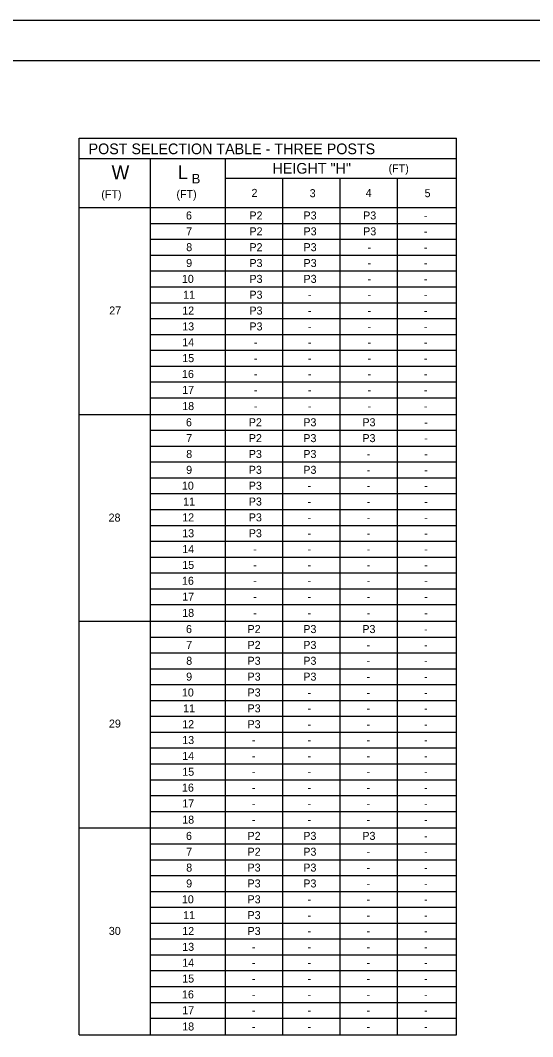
# Model space of a CAD drawing. Extents: x -2340 to 628, y -879 to 309.
# Drawn here: x -61.9 to 130.1, y -71.4 to 309.4 of the extents above; entities that cross this region are included whole.
import ezdxf

# ---------------------------------------------------------------- set-up
doc = ezdxf.new("R2010")
doc.units = 0
for name, color, linetype in [('Level 1', 7, 'Continuous'), ('Level 2', 7, 'Continuous'), ('PLT-BNDY', 7, 'Continuous')]:
    doc.layers.add(name, color=color, linetype=linetype)

msp = doc.modelspace()

# ---------------------------------------------------------------- linework, layer by layer
at = {"layer": 'Level 1'}
for p, q in [((-236.39, 294.44), (549.61, 294.44)), ((-39.86, 239.28), (-39.86, 265.3)), ((-39.86, 265.3), (101.61, 265.3)), ((101.61, 239.28), (101.61, 265.3)), ((-39.86, 257.63), (101.61, 257.63)), ((-13.06, -70.68), (-13.06, 257.63)), ((14.94, 239.28), (14.94, 257.63)), ((36.44, -70.68), (36.44, 250.28)), ((57.94, -70.68), (57.94, 250.28)), ((79.44, -70.68), (79.44, 250.28)), ((-39.86, -70.68), (-39.86, 239.28)), ((-39.86, 239.28), (101.61, 239.28)), ((14.94, -70.68), (14.94, 239.28)), ((101.61, -70.68), (101.61, 239.28))]:
    msp.add_line(p, q, dxfattribs=at)
at = {"layer": 'Level 2'}
for p, q in [((14.94, 250.28), (101.61, 250.28)), ((-13.06, 233.34), (101.61, 233.34)), ((-13.06, 227.4), (101.61, 227.4)), ((-13.06, 221.46), (101.61, 221.46)), ((53.29, 221.46), (97.57, 221.46)), ((-13.06, 215.52), (101.61, 215.52)), ((53.29, 215.52), (97.57, 215.52)), ((-13.06, 209.58), (101.61, 209.58)), ((53.29, 209.58), (97.57, 209.58)), ((-13.06, 203.64), (101.61, 203.64)), ((53.29, 203.64), (97.57, 203.64)), ((-13.06, 197.7), (101.61, 197.7)), ((53.29, 197.7), (97.57, 197.7)), ((-13.06, 191.76), (101.61, 191.76)), ((53.29, 191.76), (97.57, 191.76)), ((-13.06, 185.82), (101.61, 185.82)), ((53.29, 185.82), (97.57, 185.82)), ((-13.06, 179.88), (101.61, 179.88)), ((53.29, 179.88), (97.57, 179.88)), ((-13.06, 173.94), (101.61, 173.94)), ((53.29, 173.94), (97.57, 173.94)), ((-13.06, 168), (101.61, 168)), ((-39.86, 161.79), (101.61, 161.79)), ((-13.06, 155.85), (101.61, 155.85)), ((-13.06, 149.91), (101.61, 149.91)), ((53.29, 149.91), (97.57, 149.91)), ((-13.06, 143.97), (101.61, 143.97)), ((-13.06, 138.03), (101.61, 138.03)), ((53.29, 138.03), (97.57, 138.03)), ((-13.06, 132.09), (101.61, 132.09)), ((53.29, 132.09), (97.57, 132.09)), ((-13.06, 126.15), (101.61, 126.15)), ((-13.06, 120.21), (101.61, 120.21)), ((-13.06, 114.27), (101.61, 114.27)), ((-13.06, 108.33), (101.61, 108.33)), ((-13.06, 102.39), (101.61, 102.39)), ((-13.06, 96.45), (101.61, 96.45)), ((-13.06, 90.51), (101.61, 90.51)), ((-39.86, 84.3), (101.61, 84.3)), ((-13.06, 78.36), (101.61, 78.36)), ((-13.06, 72.42), (101.61, 72.42)), ((-13.06, 66.48), (101.61, 66.48)), ((97.57, 66.48), (101.61, 66.48)), ((-13.06, 60.54), (101.61, 60.54)), ((-13.06, 54.6), (101.61, 54.6)), ((-13.06, 48.66), (101.61, 48.66)), ((-13.06, 42.72), (101.61, 42.72)), ((-13.06, 36.78), (101.61, 36.78)), ((-13.06, 30.84), (101.61, 30.84)), ((-13.06, 24.9), (101.61, 24.9)), ((-13.06, 18.96), (101.61, 18.96)), ((-13.06, 13.02), (101.61, 13.02)), ((-39.86, 6.81), (101.61, 6.81)), ((-13.06, 0.87), (101.61, 0.87)), ((-13.06, -5.07), (101.61, -5.07)), ((-13.06, -11.01), (101.61, -11.01)), ((-13.06, -16.95), (101.61, -16.95)), ((-13.06, -22.89), (101.61, -22.89)), ((-13.06, -28.83), (101.61, -28.83)), ((-13.06, -34.77), (101.61, -34.77)), ((-13.06, -40.71), (101.61, -40.71)), ((-13.06, -46.65), (101.61, -46.65)), ((-13.06, -52.59), (101.61, -52.59)), ((-13.06, -58.53), (101.61, -58.53)), ((-13.06, -64.47), (101.61, -64.47)), ((-39.86, -70.68), (101.61, -70.68))]:
    msp.add_line(p, q, dxfattribs=at)
at = {"layer": 'PLT-BNDY'}
msp.add_lwpolyline([(-276.39, 309.44), (564.61, 309.44), (564.61, -284.56), (-276.39, -284.56)], close=True, dxfattribs=at)

# ---------------------------------------------------------------- texts
at = {"layer": 'Level 1'}
for s, height, p in [('POST SELECTION TABLE - THREE POSTS', 4.003, (-36.3, 259.28)), ('HEIGHT "H"', 4.003, (32.63, 251.98)), ('(FT)', 3, (76.11, 252.49)), ('W', 5.25, (-27.68, 249.85)), ('L', 5.16, (-2.92, 249.96)), ('B', 3.6, (2.36, 248.3)), ('(FT)', 3, (-31.53, 242.76)), ('(FT)', 3, (-3.39, 242.82))]:
    msp.add_text(s, height=height, dxfattribs=at).set_placement(p)
for s, p in [('2', (24.75, 243.27)), ('3', (46.54, 243.17)), ('4', (67.52, 243.27)), ('5', (89.59, 243.17))]:
    msp.add_text(s, height=3, rotation=360, dxfattribs=at).set_placement(p)
at = {"layer": 'Level 2'}
for s, p in [('6', (0.19, 234.82)), ('P2', (23.96, 234.82)), ('P3', (44.23, 234.82)), ('P3', (66.57, 234.82)), ('-', (89.28, 234.82)), ('7', (0.28, 228.88)), ('P2', (23.96, 228.88)), ('P3', (44.23, 228.88)), ('P3', (66.57, 228.88)), ('-', (89.28, 228.88)), ('8', (0.28, 222.94)), ('P2', (23.96, 222.94)), ('P3', (44.23, 222.94)), ('-', (68.19, 222.94)), ('-', (89.28, 222.94)), ('9', (0.26, 217)), ('P3', (23.96, 217)), ('P3', (44.23, 217)), ('-', (68.19, 217)), ('-', (89.28, 217)), ('10', (-1.35, 211.06)), ('P3', (23.96, 211.06)), ('P3', (44.23, 211.06)), ('-', (68.19, 211.06)), ('-', (89.28, 211.06)), ('11', (-0.88, 205.12)), ('P3', (23.96, 205.12)), ('-', (45.84, 205.12)), ('-', (68.19, 205.12)), ('-', (89.28, 205.12)), ('27', (-28.56, 199.21)), ('12', (-1.22, 199.18)), ('P3', (23.96, 199.18)), ('-', (45.84, 199.18)), ('-', (68.19, 199.18)), ('-', (89.28, 199.18)), ('13', (-1.22, 193.24)), ('P3', (23.96, 193.24)), ('-', (45.84, 193.24)), ('-', (68.19, 193.24)), ('-', (89.28, 193.24)), ('14', (-1.22, 187.3)), ('-', (25.58, 187.3)), ('-', (45.84, 187.3)), ('-', (68.19, 187.3)), ('-', (89.28, 187.3)), ('15', (-1.22, 181.36)), ('-', (25.58, 181.36)), ('-', (45.84, 181.36)), ('-', (68.19, 181.36)), ('-', (89.28, 181.36)), ('16', (-1.31, 175.42)), ('-', (25.58, 175.42)), ('-', (45.84, 175.42)), ('-', (68.19, 175.42)), ('-', (89.28, 175.42)), ('17', (-1.22, 169.48)), ('-', (25.58, 169.48)), ('-', (45.84, 169.48)), ('-', (68.19, 169.48)), ('-', (89.28, 169.48)), ('18', (-1.22, 163.4)), ('-', (25.58, 163.4)), ('-', (45.84, 163.4)), ('-', (68.19, 163.4)), ('-', (89.28, 163.4)), ('6', (0.19, 157.33)), ('P2', (23.72, 157.33)), ('P3', (44.15, 157.33)), ('P3', (66.29, 157.33)), ('-', (89.49, 157.33)), ('7', (0.28, 151.39)), ('P2', (23.72, 151.39)), ('P3', (44.15, 151.39)), ('P3', (66.29, 151.39)), ('-', (89.49, 151.39)), ('8', (0.28, 145.45)), ('P3', (23.72, 145.45)), ('P3', (44.15, 145.45)), ('-', (67.91, 145.45)), ('-', (89.49, 145.45)), ('9', (0.26, 139.51)), ('P3', (23.72, 139.51)), ('P3', (44.15, 139.51)), ('-', (67.91, 139.51)), ('-', (89.49, 139.51)), ('10', (-1.35, 133.57)), ('P3', (23.72, 133.57)), ('-', (45.77, 133.57)), ('-', (67.91, 133.57)), ('-', (89.49, 133.57)), ('11', (-0.88, 127.63)), ('P3', (23.72, 127.63)), ('-', (45.77, 127.63)), ('-', (67.91, 127.63)), ('-', (89.49, 127.63)), ('28', (-28.81, 121.62)), ('12', (-1.22, 121.69)), ('P3', (23.72, 121.69)), ('-', (45.77, 121.69)), ('-', (67.91, 121.69)), ('-', (89.49, 121.69)), ('13', (-1.22, 115.75)), ('P3', (23.72, 115.75)), ('-', (45.77, 115.75)), ('-', (67.91, 115.75)), ('-', (89.49, 115.75)), ('14', (-1.22, 109.81)), ('-', (25.34, 109.81)), ('-', (45.77, 109.81)), ('-', (67.91, 109.81)), ('-', (89.49, 109.81)), ('15', (-1.22, 103.87)), ('-', (25.34, 103.87)), ('-', (45.77, 103.87)), ('-', (67.91, 103.87)), ('-', (89.49, 103.87)), ('16', (-1.31, 97.93)), ('-', (25.34, 97.93)), ('-', (45.77, 97.93)), ('-', (67.91, 97.93)), ('-', (89.49, 97.93)), ('17', (-1.22, 91.99)), ('-', (25.34, 91.99)), ('-', (45.77, 91.99)), ('-', (67.91, 91.99)), ('-', (89.49, 91.99)), ('18', (-1.22, 85.91)), ('-', (25.34, 85.91)), ('-', (45.77, 85.91)), ('-', (67.91, 85.91)), ('-', (89.49, 85.91)), ('6', (0.19, 79.84)), ('P2', (23.25, 79.84)), ('P3', (44.15, 79.84)), ('P3', (66.27, 79.84)), ('-', (89.39, 79.84)), ('7', (0.28, 73.9)), ('P2', (23.25, 73.9)), ('P3', (44.15, 73.9)), ('-', (67.89, 73.9)), ('-', (89.39, 73.9)), ('8', (0.28, 67.96)), ('P3', (23.25, 67.96)), ('P3', (44.15, 67.96)), ('-', (67.89, 67.96)), ('-', (89.39, 67.96)), ('9', (0.26, 62.02)), ('P3', (23.25, 62.02)), ('P3', (44.15, 62.02)), ('-', (67.89, 62.02)), ('-', (89.39, 62.02)), ('10', (-1.35, 56.08)), ('P3', (23.25, 56.08)), ('-', (45.77, 56.08)), ('-', (67.89, 56.08)), ('-', (89.39, 56.08)), ('11', (-0.88, 50.14)), ('P3', (23.25, 50.14)), ('-', (45.77, 50.14)), ('-', (67.89, 50.14)), ('-', (89.39, 50.14)), ('29', (-28.68, 44.43)), ('12', (-1.22, 44.2)), ('P3', (23.25, 44.2)), ('-', (45.77, 44.2)), ('-', (67.89, 44.2)), ('-', (89.39, 44.2)), ('13', (-1.22, 38.26)), ('-', (24.87, 38.26)), ('-', (45.77, 38.26)), ('-', (67.89, 38.26)), ('-', (89.39, 38.26)), ('14', (-1.22, 32.32)), ('-', (24.87, 32.32)), ('-', (45.77, 32.32)), ('-', (67.89, 32.32)), ('-', (89.39, 32.32)), ('15', (-1.22, 26.38)), ('-', (24.87, 26.38)), ('-', (45.77, 26.38)), ('-', (67.89, 26.38)), ('-', (89.39, 26.38)), ('16', (-1.31, 20.44)), ('-', (24.87, 20.44)), ('-', (45.77, 20.44)), ('-', (67.89, 20.44)), ('-', (89.39, 20.44)), ('17', (-1.22, 14.5)), ('-', (24.87, 14.5)), ('-', (45.77, 14.5)), ('-', (67.89, 14.5)), ('-', (89.39, 14.5)), ('18', (-1.22, 8.42)), ('-', (24.87, 8.42)), ('-', (45.77, 8.42)), ('-', (67.89, 8.42)), ('-', (89.39, 8.42)), ('6', (0.19, 2.35)), ('P2', (23.25, 2.35)), ('P3', (44.15, 2.35)), ('P3', (66.27, 2.35)), ('-', (89.39, 2.35)), ('7', (0.28, -3.59)), ('P2', (23.25, -3.59)), ('P3', (44.15, -3.59)), ('-', (67.89, -3.59)), ('-', (89.39, -3.59)), ('8', (0.28, -9.53)), ('P3', (23.25, -9.53)), ('P3', (44.15, -9.53)), ('-', (67.89, -9.53)), ('-', (89.39, -9.53)), ('9', (0.26, -15.47)), ('P3', (23.25, -15.47)), ('P3', (44.15, -15.47)), ('-', (67.89, -15.47)), ('-', (89.39, -15.47)), ('10', (-1.35, -21.41)), ('P3', (23.25, -21.41)), ('-', (45.77, -21.41)), ('-', (67.89, -21.41)), ('-', (89.39, -21.41)), ('11', (-0.88, -27.35)), ('P3', (23.25, -27.35)), ('-', (45.77, -27.35)), ('-', (67.89, -27.35)), ('-', (89.39, -27.35)), ('30', (-28.72, -33.26)), ('12', (-1.22, -33.29)), ('P3', (23.25, -33.29)), ('-', (45.77, -33.29)), ('-', (67.89, -33.29)), ('-', (89.39, -33.29)), ('13', (-1.22, -39.23)), ('-', (24.87, -39.23)), ('-', (45.77, -39.23)), ('-', (67.89, -39.23)), ('-', (89.39, -39.23)), ('14', (-1.22, -45.17)), ('-', (24.87, -45.17)), ('-', (45.77, -45.17)), ('-', (67.89, -45.17)), ('-', (89.39, -45.17)), ('15', (-1.22, -51.11)), ('-', (24.87, -51.11)), ('-', (45.77, -51.11)), ('-', (67.89, -51.11)), ('-', (89.39, -51.11)), ('16', (-1.31, -57.05)), ('-', (24.87, -57.05)), ('-', (45.77, -57.05)), ('-', (67.89, -57.05)), ('-', (89.39, -57.05)), ('17', (-1.22, -62.99)), ('-', (24.87, -62.99)), ('-', (45.77, -62.99)), ('-', (67.89, -62.99)), ('-', (89.39, -62.99)), ('18', (-1.22, -69.07)), ('-', (24.87, -69.07)), ('-', (45.77, -69.07)), ('-', (67.89, -69.07)), ('-', (89.39, -69.07))]:
    msp.add_text(s, height=3, dxfattribs=at).set_placement(p)

doc.saveas('drawing.dxf')
